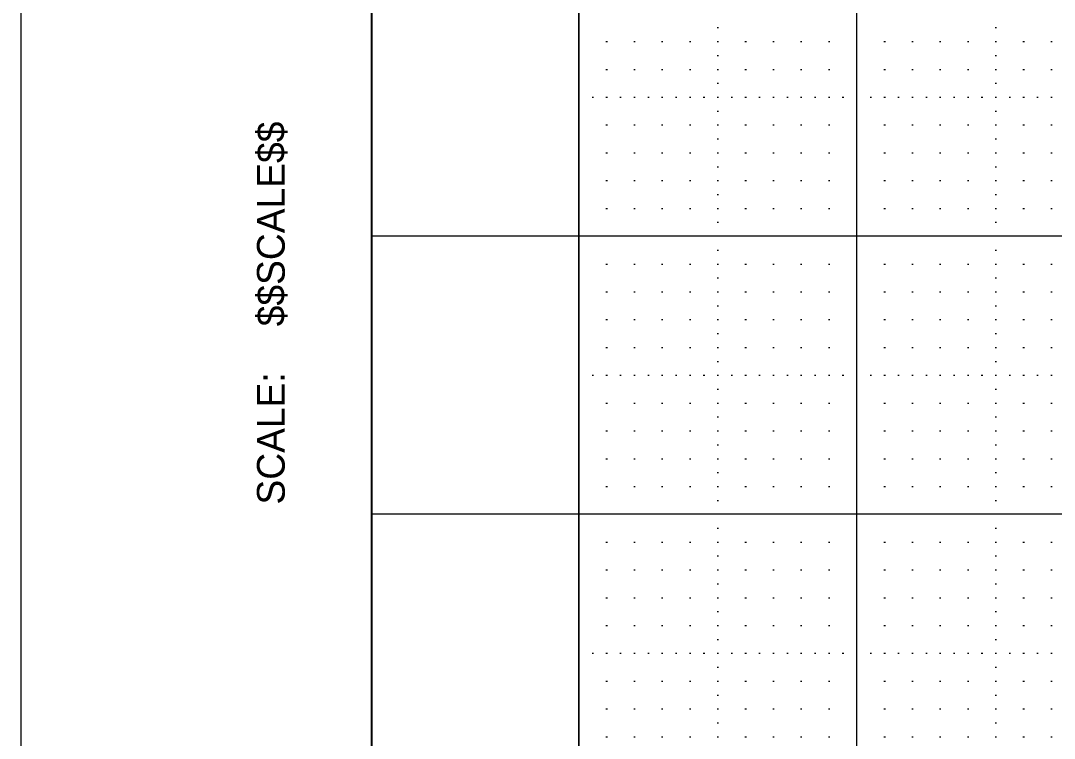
# Model space of a CAD drawing. Extents: x -1.3 to 32.1, y -0.2 to 20.7.
# Drawn here: x -1.263 to 2.455, y 2.487 to 5.068 of the extents above; entities that cross this region are included whole.
import ezdxf

# ---------------------------------------------------------------- set-up
doc = ezdxf.new("R2010")
doc.units = 0
for name, color, linetype in [('Level 1', 7, 'Continuous'), ('Level 37', 7, 'Continuous'), ('Level 4', 7, 'Continuous'), ('Level 5', 7, 'Continuous'), ('Level 62', 7, 'Continuous'), ('Level 63', 7, 'Continuous')]:
    doc.layers.add(name, color=color, linetype=linetype)

msp = doc.modelspace()

# ---------------------------------------------------------------- linework, layer by layer
at = {"layer": 'Level 1'}
msp.add_line((-0.001, -0.001), (-0.001, 20.545), dxfattribs=at)
at = {"layer": 'Level 37'}
msp.add_line((0.746, 0.6725), (0.746, 10.2935), dxfattribs=at)
at = {"layer": 'Level 4'}
for p, q in [((0.745, 0.672), (0.745, 10.293)), ((1.745, 0.672), (1.745, 10.293)), ((31.617, 4.293), (-0.001, 4.293)), ((31.617, 3.293), (-0.001, 3.293))]:
    msp.add_line(p, q, dxfattribs=at)
at = {"layer": 'Level 5'}
for p, q in [((1.2425, 5.043), (1.2475, 5.043)), ((2.2425, 5.043), (2.2475, 5.043)), ((0.8425, 4.993), (0.8475, 4.993)), ((0.9425, 4.993), (0.9475, 4.993)), ((1.0425, 4.993), (1.0475, 4.993)), ((1.1425, 4.993), (1.1475, 4.993)), ((1.2425, 4.993), (1.2475, 4.993)), ((1.3425, 4.993), (1.3475, 4.993)), ((1.4425, 4.993), (1.4475, 4.993)), ((1.5425, 4.993), (1.5475, 4.993)), ((1.6425, 4.993), (1.6475, 4.993)), ((1.8425, 4.993), (1.8475, 4.993)), ((1.9425, 4.993), (1.9475, 4.993)), ((2.0425, 4.993), (2.0475, 4.993)), ((2.1425, 4.993), (2.1475, 4.993)), ((2.2425, 4.993), (2.2475, 4.993)), ((2.3425, 4.993), (2.3475, 4.993)), ((2.4425, 4.993), (2.4475, 4.993)), ((1.2425, 4.943), (1.2475, 4.943)), ((2.2425, 4.943), (2.2475, 4.943)), ((0.8425, 4.893), (0.8475, 4.893)), ((0.9425, 4.893), (0.9475, 4.893)), ((1.0425, 4.893), (1.0475, 4.893)), ((1.1425, 4.893), (1.1475, 4.893)), ((1.2425, 4.893), (1.2475, 4.893)), ((1.3425, 4.893), (1.3475, 4.893)), ((1.4425, 4.893), (1.4475, 4.893)), ((1.5425, 4.893), (1.5475, 4.893)), ((1.6425, 4.893), (1.6475, 4.893)), ((1.8425, 4.893), (1.8475, 4.893)), ((1.9425, 4.893), (1.9475, 4.893)), ((2.0425, 4.893), (2.0475, 4.893)), ((2.1425, 4.893), (2.1475, 4.893)), ((2.2425, 4.893), (2.2475, 4.893)), ((2.3425, 4.893), (2.3475, 4.893)), ((2.4425, 4.893), (2.4475, 4.893)), ((1.2425, 4.843), (1.2475, 4.843)), ((2.2425, 4.843), (2.2475, 4.843)), ((0.7925, 4.793), (0.7975, 4.793)), ((0.8425, 4.793), (0.8475, 4.793)), ((0.8925, 4.793), (0.8975, 4.793)), ((0.9425, 4.793), (0.9475, 4.793)), ((0.9925, 4.793), (0.9975, 4.793)), ((1.0425, 4.793), (1.0475, 4.793)), ((1.0925, 4.793), (1.0975, 4.793)), ((1.1425, 4.793), (1.1475, 4.793)), ((1.1925, 4.793), (1.1975, 4.793)), ((1.2425, 4.793), (1.2475, 4.793)), ((1.2925, 4.793), (1.2975, 4.793)), ((1.3425, 4.793), (1.3475, 4.793)), ((1.3925, 4.793), (1.3975, 4.793)), ((1.4425, 4.793), (1.4475, 4.793)), ((1.4925, 4.793), (1.4975, 4.793)), ((1.5425, 4.793), (1.5475, 4.793)), ((1.5925, 4.793), (1.5975, 4.793)), ((1.6425, 4.793), (1.6475, 4.793)), ((1.6925, 4.793), (1.6975, 4.793)), ((1.7925, 4.793), (1.7975, 4.793)), ((1.8425, 4.793), (1.8475, 4.793)), ((1.8925, 4.793), (1.8975, 4.793)), ((1.9425, 4.793), (1.9475, 4.793)), ((1.9925, 4.793), (1.9975, 4.793)), ((2.0425, 4.793), (2.0475, 4.793)), ((2.0925, 4.793), (2.0975, 4.793)), ((2.1425, 4.793), (2.1475, 4.793)), ((2.1925, 4.793), (2.1975, 4.793)), ((2.2425, 4.793), (2.2475, 4.793)), ((2.2925, 4.793), (2.2975, 4.793)), ((2.3425, 4.793), (2.3475, 4.793)), ((2.3925, 4.793), (2.3975, 4.793)), ((2.4425, 4.793), (2.4475, 4.793)), ((1.2425, 4.743), (1.2475, 4.743)), ((2.2425, 4.743), (2.2475, 4.743)), ((0.8425, 4.693), (0.8475, 4.693)), ((0.9425, 4.693), (0.9475, 4.693)), ((1.0425, 4.693), (1.0475, 4.693)), ((1.1425, 4.693), (1.1475, 4.693)), ((1.2425, 4.693), (1.2475, 4.693)), ((1.3425, 4.693), (1.3475, 4.693)), ((1.4425, 4.693), (1.4475, 4.693)), ((1.5425, 4.693), (1.5475, 4.693)), ((1.6425, 4.693), (1.6475, 4.693)), ((1.8425, 4.693), (1.8475, 4.693)), ((1.9425, 4.693), (1.9475, 4.693)), ((2.0425, 4.693), (2.0475, 4.693)), ((2.1425, 4.693), (2.1475, 4.693)), ((2.2425, 4.693), (2.2475, 4.693)), ((2.3425, 4.693), (2.3475, 4.693)), ((2.4425, 4.693), (2.4475, 4.693)), ((1.2425, 4.643), (1.2475, 4.643)), ((2.2425, 4.643), (2.2475, 4.643)), ((0.8425, 4.593), (0.8475, 4.593)), ((0.9425, 4.593), (0.9475, 4.593)), ((1.0425, 4.593), (1.0475, 4.593)), ((1.1425, 4.593), (1.1475, 4.593)), ((1.2425, 4.593), (1.2475, 4.593)), ((1.3425, 4.593), (1.3475, 4.593)), ((1.4425, 4.593), (1.4475, 4.593)), ((1.5425, 4.593), (1.5475, 4.593)), ((1.6425, 4.593), (1.6475, 4.593)), ((1.8425, 4.593), (1.8475, 4.593)), ((1.9425, 4.593), (1.9475, 4.593)), ((2.0425, 4.593), (2.0475, 4.593)), ((2.1425, 4.593), (2.1475, 4.593)), ((2.2425, 4.593), (2.2475, 4.593)), ((2.3425, 4.593), (2.3475, 4.593)), ((2.4425, 4.593), (2.4475, 4.593)), ((1.2425, 4.543), (1.2475, 4.543)), ((2.2425, 4.543), (2.2475, 4.543)), ((0.8425, 4.493), (0.8475, 4.493)), ((0.9425, 4.493), (0.9475, 4.493)), ((1.0425, 4.493), (1.0475, 4.493)), ((1.1425, 4.493), (1.1475, 4.493)), ((1.2425, 4.493), (1.2475, 4.493)), ((1.3425, 4.493), (1.3475, 4.493)), ((1.4425, 4.493), (1.4475, 4.493)), ((1.5425, 4.493), (1.5475, 4.493)), ((1.6425, 4.493), (1.6475, 4.493)), ((1.8425, 4.493), (1.8475, 4.493)), ((1.9425, 4.493), (1.9475, 4.493)), ((2.0425, 4.493), (2.0475, 4.493)), ((2.1425, 4.493), (2.1475, 4.493)), ((2.2425, 4.493), (2.2475, 4.493)), ((2.3425, 4.493), (2.3475, 4.493)), ((2.4425, 4.493), (2.4475, 4.493)), ((1.2425, 4.443), (1.2475, 4.443)), ((2.2425, 4.443), (2.2475, 4.443)), ((0.8425, 4.393), (0.8475, 4.393)), ((0.9425, 4.393), (0.9475, 4.393)), ((1.0425, 4.393), (1.0475, 4.393)), ((1.1425, 4.393), (1.1475, 4.393)), ((1.2425, 4.393), (1.2475, 4.393)), ((1.3425, 4.393), (1.3475, 4.393)), ((1.4425, 4.393), (1.4475, 4.393)), ((1.5425, 4.393), (1.5475, 4.393)), ((1.6425, 4.393), (1.6475, 4.393)), ((1.8425, 4.393), (1.8475, 4.393)), ((1.9425, 4.393), (1.9475, 4.393)), ((2.0425, 4.393), (2.0475, 4.393)), ((2.1425, 4.393), (2.1475, 4.393)), ((2.2425, 4.393), (2.2475, 4.393)), ((2.3425, 4.393), (2.3475, 4.393)), ((2.4425, 4.393), (2.4475, 4.393)), ((1.2425, 4.343), (1.2475, 4.343)), ((2.2425, 4.343), (2.2475, 4.343)), ((1.2425, 4.243), (1.2475, 4.243)), ((2.2425, 4.243), (2.2475, 4.243)), ((0.8425, 4.193), (0.8475, 4.193)), ((0.9425, 4.193), (0.9475, 4.193)), ((1.0425, 4.193), (1.0475, 4.193)), ((1.1425, 4.193), (1.1475, 4.193)), ((1.2425, 4.193), (1.2475, 4.193)), ((1.3425, 4.193), (1.3475, 4.193)), ((1.4425, 4.193), (1.4475, 4.193)), ((1.5425, 4.193), (1.5475, 4.193)), ((1.6425, 4.193), (1.6475, 4.193)), ((1.8425, 4.193), (1.8475, 4.193)), ((1.9425, 4.193), (1.9475, 4.193)), ((2.0425, 4.193), (2.0475, 4.193)), ((2.1425, 4.193), (2.1475, 4.193)), ((2.2425, 4.193), (2.2475, 4.193)), ((2.3425, 4.193), (2.3475, 4.193)), ((2.4425, 4.193), (2.4475, 4.193)), ((1.2425, 4.143), (1.2475, 4.143)), ((2.2425, 4.143), (2.2475, 4.143)), ((0.8425, 4.093), (0.8475, 4.093)), ((0.9425, 4.093), (0.9475, 4.093)), ((1.0425, 4.093), (1.0475, 4.093)), ((1.1425, 4.093), (1.1475, 4.093)), ((1.2425, 4.093), (1.2475, 4.093)), ((1.3425, 4.093), (1.3475, 4.093)), ((1.4425, 4.093), (1.4475, 4.093)), ((1.5425, 4.093), (1.5475, 4.093)), ((1.6425, 4.093), (1.6475, 4.093)), ((1.8425, 4.093), (1.8475, 4.093)), ((1.9425, 4.093), (1.9475, 4.093)), ((2.0425, 4.093), (2.0475, 4.093)), ((2.1425, 4.093), (2.1475, 4.093)), ((2.2425, 4.093), (2.2475, 4.093)), ((2.3425, 4.093), (2.3475, 4.093)), ((2.4425, 4.093), (2.4475, 4.093)), ((1.2425, 4.043), (1.2475, 4.043)), ((2.2425, 4.043), (2.2475, 4.043)), ((0.8425, 3.993), (0.8475, 3.993)), ((0.9425, 3.993), (0.9475, 3.993)), ((1.0425, 3.993), (1.0475, 3.993)), ((1.1425, 3.993), (1.1475, 3.993)), ((1.2425, 3.993), (1.2475, 3.993)), ((1.3425, 3.993), (1.3475, 3.993)), ((1.4425, 3.993), (1.4475, 3.993)), ((1.5425, 3.993), (1.5475, 3.993)), ((1.6425, 3.993), (1.6475, 3.993)), ((1.8425, 3.993), (1.8475, 3.993)), ((1.9425, 3.993), (1.9475, 3.993)), ((2.0425, 3.993), (2.0475, 3.993)), ((2.1425, 3.993), (2.1475, 3.993)), ((2.2425, 3.993), (2.2475, 3.993)), ((2.3425, 3.993), (2.3475, 3.993)), ((2.4425, 3.993), (2.4475, 3.993)), ((1.2425, 3.943), (1.2475, 3.943)), ((2.2425, 3.943), (2.2475, 3.943)), ((0.8425, 3.893), (0.8475, 3.893)), ((0.9425, 3.893), (0.9475, 3.893)), ((1.0425, 3.893), (1.0475, 3.893)), ((1.1425, 3.893), (1.1475, 3.893)), ((1.2425, 3.893), (1.2475, 3.893)), ((1.3425, 3.893), (1.3475, 3.893)), ((1.4425, 3.893), (1.4475, 3.893)), ((1.5425, 3.893), (1.5475, 3.893)), ((1.6425, 3.893), (1.6475, 3.893)), ((1.8425, 3.893), (1.8475, 3.893)), ((1.9425, 3.893), (1.9475, 3.893)), ((2.0425, 3.893), (2.0475, 3.893)), ((2.1425, 3.893), (2.1475, 3.893)), ((2.2425, 3.893), (2.2475, 3.893)), ((2.3425, 3.893), (2.3475, 3.893)), ((2.4425, 3.893), (2.4475, 3.893)), ((1.2425, 3.843), (1.2475, 3.843)), ((2.2425, 3.843), (2.2475, 3.843)), ((0.7925, 3.793), (0.7975, 3.793)), ((0.8425, 3.793), (0.8475, 3.793)), ((0.8925, 3.793), (0.8975, 3.793)), ((0.9425, 3.793), (0.9475, 3.793)), ((0.9925, 3.793), (0.9975, 3.793)), ((1.0425, 3.793), (1.0475, 3.793)), ((1.0925, 3.793), (1.0975, 3.793)), ((1.1425, 3.793), (1.1475, 3.793)), ((1.1925, 3.793), (1.1975, 3.793)), ((1.2425, 3.793), (1.2475, 3.793)), ((1.2925, 3.793), (1.2975, 3.793)), ((1.3425, 3.793), (1.3475, 3.793)), ((1.3925, 3.793), (1.3975, 3.793)), ((1.4425, 3.793), (1.4475, 3.793)), ((1.4925, 3.793), (1.4975, 3.793)), ((1.5425, 3.793), (1.5475, 3.793)), ((1.5925, 3.793), (1.5975, 3.793)), ((1.6425, 3.793), (1.6475, 3.793)), ((1.6925, 3.793), (1.6975, 3.793)), ((1.7925, 3.793), (1.7975, 3.793)), ((1.8425, 3.793), (1.8475, 3.793)), ((1.8925, 3.793), (1.8975, 3.793)), ((1.9425, 3.793), (1.9475, 3.793)), ((1.9925, 3.793), (1.9975, 3.793)), ((2.0425, 3.793), (2.0475, 3.793)), ((2.0925, 3.793), (2.0975, 3.793)), ((2.1425, 3.793), (2.1475, 3.793)), ((2.1925, 3.793), (2.1975, 3.793)), ((2.2425, 3.793), (2.2475, 3.793)), ((2.2925, 3.793), (2.2975, 3.793)), ((2.3425, 3.793), (2.3475, 3.793)), ((2.3925, 3.793), (2.3975, 3.793)), ((2.4425, 3.793), (2.4475, 3.793)), ((1.2425, 3.743), (1.2475, 3.743)), ((2.2425, 3.743), (2.2475, 3.743)), ((0.8425, 3.693), (0.8475, 3.693)), ((0.9425, 3.693), (0.9475, 3.693)), ((1.0425, 3.693), (1.0475, 3.693)), ((1.1425, 3.693), (1.1475, 3.693)), ((1.2425, 3.693), (1.2475, 3.693)), ((1.3425, 3.693), (1.3475, 3.693)), ((1.4425, 3.693), (1.4475, 3.693)), ((1.5425, 3.693), (1.5475, 3.693)), ((1.6425, 3.693), (1.6475, 3.693)), ((1.8425, 3.693), (1.8475, 3.693)), ((1.9425, 3.693), (1.9475, 3.693)), ((2.0425, 3.693), (2.0475, 3.693)), ((2.1425, 3.693), (2.1475, 3.693)), ((2.2425, 3.693), (2.2475, 3.693)), ((2.3425, 3.693), (2.3475, 3.693)), ((2.4425, 3.693), (2.4475, 3.693)), ((1.2425, 3.643), (1.2475, 3.643)), ((2.2425, 3.643), (2.2475, 3.643)), ((0.8425, 3.593), (0.8475, 3.593)), ((0.9425, 3.593), (0.9475, 3.593)), ((1.0425, 3.593), (1.0475, 3.593)), ((1.1425, 3.593), (1.1475, 3.593)), ((1.2425, 3.593), (1.2475, 3.593)), ((1.3425, 3.593), (1.3475, 3.593)), ((1.4425, 3.593), (1.4475, 3.593)), ((1.5425, 3.593), (1.5475, 3.593)), ((1.6425, 3.593), (1.6475, 3.593)), ((1.8425, 3.593), (1.8475, 3.593)), ((1.9425, 3.593), (1.9475, 3.593)), ((2.0425, 3.593), (2.0475, 3.593)), ((2.1425, 3.593), (2.1475, 3.593)), ((2.2425, 3.593), (2.2475, 3.593)), ((2.3425, 3.593), (2.3475, 3.593)), ((2.4425, 3.593), (2.4475, 3.593)), ((1.2425, 3.543), (1.2475, 3.543)), ((2.2425, 3.543), (2.2475, 3.543)), ((0.8425, 3.493), (0.8475, 3.493)), ((0.9425, 3.493), (0.9475, 3.493)), ((1.0425, 3.493), (1.0475, 3.493)), ((1.1425, 3.493), (1.1475, 3.493)), ((1.2425, 3.493), (1.2475, 3.493)), ((1.3425, 3.493), (1.3475, 3.493)), ((1.4425, 3.493), (1.4475, 3.493)), ((1.5425, 3.493), (1.5475, 3.493)), ((1.6425, 3.493), (1.6475, 3.493)), ((1.8425, 3.493), (1.8475, 3.493)), ((1.9425, 3.493), (1.9475, 3.493)), ((2.0425, 3.493), (2.0475, 3.493)), ((2.1425, 3.493), (2.1475, 3.493)), ((2.2425, 3.493), (2.2475, 3.493)), ((2.3425, 3.493), (2.3475, 3.493)), ((2.4425, 3.493), (2.4475, 3.493)), ((1.2425, 3.443), (1.2475, 3.443)), ((2.2425, 3.443), (2.2475, 3.443)), ((0.8425, 3.393), (0.8475, 3.393)), ((0.9425, 3.393), (0.9475, 3.393)), ((1.0425, 3.393), (1.0475, 3.393)), ((1.1425, 3.393), (1.1475, 3.393)), ((1.2425, 3.393), (1.2475, 3.393)), ((1.3425, 3.393), (1.3475, 3.393)), ((1.4425, 3.393), (1.4475, 3.393)), ((1.5425, 3.393), (1.5475, 3.393)), ((1.6425, 3.393), (1.6475, 3.393)), ((1.8425, 3.393), (1.8475, 3.393)), ((1.9425, 3.393), (1.9475, 3.393)), ((2.0425, 3.393), (2.0475, 3.393)), ((2.1425, 3.393), (2.1475, 3.393)), ((2.2425, 3.393), (2.2475, 3.393)), ((2.3425, 3.393), (2.3475, 3.393)), ((2.4425, 3.393), (2.4475, 3.393)), ((1.2425, 3.343), (1.2475, 3.343)), ((2.2425, 3.343), (2.2475, 3.343)), ((1.2425, 3.243), (1.2475, 3.243)), ((2.2425, 3.243), (2.2475, 3.243)), ((0.8425, 3.193), (0.8475, 3.193)), ((0.9425, 3.193), (0.9475, 3.193)), ((1.0425, 3.193), (1.0475, 3.193)), ((1.1425, 3.193), (1.1475, 3.193)), ((1.2425, 3.193), (1.2475, 3.193)), ((1.3425, 3.193), (1.3475, 3.193)), ((1.4425, 3.193), (1.4475, 3.193)), ((1.5425, 3.193), (1.5475, 3.193)), ((1.6425, 3.193), (1.6475, 3.193)), ((1.8425, 3.193), (1.8475, 3.193)), ((1.9425, 3.193), (1.9475, 3.193)), ((2.0425, 3.193), (2.0475, 3.193)), ((2.1425, 3.193), (2.1475, 3.193)), ((2.2425, 3.193), (2.2475, 3.193)), ((2.3425, 3.193), (2.3475, 3.193)), ((2.4425, 3.193), (2.4475, 3.193)), ((1.2425, 3.143), (1.2475, 3.143)), ((2.2425, 3.143), (2.2475, 3.143)), ((0.8425, 3.093), (0.8475, 3.093)), ((0.9425, 3.093), (0.9475, 3.093)), ((1.0425, 3.093), (1.0475, 3.093)), ((1.1425, 3.093), (1.1475, 3.093)), ((1.2425, 3.093), (1.2475, 3.093)), ((1.3425, 3.093), (1.3475, 3.093)), ((1.4425, 3.093), (1.4475, 3.093)), ((1.5425, 3.093), (1.5475, 3.093)), ((1.6425, 3.093), (1.6475, 3.093)), ((1.8425, 3.093), (1.8475, 3.093)), ((1.9425, 3.093), (1.9475, 3.093)), ((2.0425, 3.093), (2.0475, 3.093)), ((2.1425, 3.093), (2.1475, 3.093)), ((2.2425, 3.093), (2.2475, 3.093)), ((2.3425, 3.093), (2.3475, 3.093)), ((2.4425, 3.093), (2.4475, 3.093)), ((1.2425, 3.043), (1.2475, 3.043)), ((2.2425, 3.043), (2.2475, 3.043)), ((0.8425, 2.993), (0.8475, 2.993)), ((0.9425, 2.993), (0.9475, 2.993)), ((1.0425, 2.993), (1.0475, 2.993)), ((1.1425, 2.993), (1.1475, 2.993)), ((1.2425, 2.993), (1.2475, 2.993)), ((1.3425, 2.993), (1.3475, 2.993)), ((1.4425, 2.993), (1.4475, 2.993)), ((1.5425, 2.993), (1.5475, 2.993)), ((1.6425, 2.993), (1.6475, 2.993)), ((1.8425, 2.993), (1.8475, 2.993)), ((1.9425, 2.993), (1.9475, 2.993)), ((2.0425, 2.993), (2.0475, 2.993)), ((2.1425, 2.993), (2.1475, 2.993)), ((2.2425, 2.993), (2.2475, 2.993)), ((2.3425, 2.993), (2.3475, 2.993)), ((2.4425, 2.993), (2.4475, 2.993)), ((1.2425, 2.943), (1.2475, 2.943)), ((2.2425, 2.943), (2.2475, 2.943)), ((0.8425, 2.893), (0.8475, 2.893)), ((0.9425, 2.893), (0.9475, 2.893)), ((1.0425, 2.893), (1.0475, 2.893)), ((1.1425, 2.893), (1.1475, 2.893)), ((1.2425, 2.893), (1.2475, 2.893)), ((1.3425, 2.893), (1.3475, 2.893)), ((1.4425, 2.893), (1.4475, 2.893)), ((1.5425, 2.893), (1.5475, 2.893)), ((1.6425, 2.893), (1.6475, 2.893)), ((1.8425, 2.893), (1.8475, 2.893)), ((1.9425, 2.893), (1.9475, 2.893)), ((2.0425, 2.893), (2.0475, 2.893)), ((2.1425, 2.893), (2.1475, 2.893)), ((2.2425, 2.893), (2.2475, 2.893)), ((2.3425, 2.893), (2.3475, 2.893)), ((2.4425, 2.893), (2.4475, 2.893)), ((1.2425, 2.843), (1.2475, 2.843)), ((2.2425, 2.843), (2.2475, 2.843)), ((0.7925, 2.793), (0.7975, 2.793)), ((0.8425, 2.793), (0.8475, 2.793)), ((0.8925, 2.793), (0.8975, 2.793)), ((0.9425, 2.793), (0.9475, 2.793)), ((0.9925, 2.793), (0.9975, 2.793)), ((1.0425, 2.793), (1.0475, 2.793)), ((1.0925, 2.793), (1.0975, 2.793)), ((1.1425, 2.793), (1.1475, 2.793)), ((1.1925, 2.793), (1.1975, 2.793)), ((1.2425, 2.793), (1.2475, 2.793)), ((1.2925, 2.793), (1.2975, 2.793)), ((1.3425, 2.793), (1.3475, 2.793)), ((1.3925, 2.793), (1.3975, 2.793)), ((1.4425, 2.793), (1.4475, 2.793)), ((1.4925, 2.793), (1.4975, 2.793)), ((1.5425, 2.793), (1.5475, 2.793)), ((1.5925, 2.793), (1.5975, 2.793)), ((1.6425, 2.793), (1.6475, 2.793)), ((1.6925, 2.793), (1.6975, 2.793)), ((1.7925, 2.793), (1.7975, 2.793)), ((1.8425, 2.793), (1.8475, 2.793)), ((1.8925, 2.793), (1.8975, 2.793)), ((1.9425, 2.793), (1.9475, 2.793)), ((1.9925, 2.793), (1.9975, 2.793)), ((2.0425, 2.793), (2.0475, 2.793)), ((2.0925, 2.793), (2.0975, 2.793)), ((2.1425, 2.793), (2.1475, 2.793)), ((2.1925, 2.793), (2.1975, 2.793)), ((2.2425, 2.793), (2.2475, 2.793)), ((2.2925, 2.793), (2.2975, 2.793)), ((2.3425, 2.793), (2.3475, 2.793)), ((2.3925, 2.793), (2.3975, 2.793)), ((2.4425, 2.793), (2.4475, 2.793)), ((1.2425, 2.743), (1.2475, 2.743)), ((2.2425, 2.743), (2.2475, 2.743)), ((0.8425, 2.693), (0.8475, 2.693)), ((0.9425, 2.693), (0.9475, 2.693)), ((1.0425, 2.693), (1.0475, 2.693)), ((1.1425, 2.693), (1.1475, 2.693)), ((1.2425, 2.693), (1.2475, 2.693)), ((1.3425, 2.693), (1.3475, 2.693)), ((1.4425, 2.693), (1.4475, 2.693)), ((1.5425, 2.693), (1.5475, 2.693)), ((1.6425, 2.693), (1.6475, 2.693)), ((1.8425, 2.693), (1.8475, 2.693)), ((1.9425, 2.693), (1.9475, 2.693)), ((2.0425, 2.693), (2.0475, 2.693)), ((2.1425, 2.693), (2.1475, 2.693)), ((2.2425, 2.693), (2.2475, 2.693)), ((2.3425, 2.693), (2.3475, 2.693)), ((2.4425, 2.693), (2.4475, 2.693)), ((1.2425, 2.643), (1.2475, 2.643)), ((2.2425, 2.643), (2.2475, 2.643)), ((0.8425, 2.593), (0.8475, 2.593)), ((0.9425, 2.593), (0.9475, 2.593)), ((1.0425, 2.593), (1.0475, 2.593)), ((1.1425, 2.593), (1.1475, 2.593)), ((1.2425, 2.593), (1.2475, 2.593)), ((1.3425, 2.593), (1.3475, 2.593)), ((1.4425, 2.593), (1.4475, 2.593)), ((1.5425, 2.593), (1.5475, 2.593)), ((1.6425, 2.593), (1.6475, 2.593)), ((1.8425, 2.593), (1.8475, 2.593)), ((1.9425, 2.593), (1.9475, 2.593)), ((2.0425, 2.593), (2.0475, 2.593)), ((2.1425, 2.593), (2.1475, 2.593)), ((2.2425, 2.593), (2.2475, 2.593)), ((2.3425, 2.593), (2.3475, 2.593)), ((2.4425, 2.593), (2.4475, 2.593)), ((1.2425, 2.543), (1.2475, 2.543)), ((2.2425, 2.543), (2.2475, 2.543)), ((0.8425, 2.493), (0.8475, 2.493)), ((0.9425, 2.493), (0.9475, 2.493)), ((1.0425, 2.493), (1.0475, 2.493)), ((1.1425, 2.493), (1.1475, 2.493)), ((1.2425, 2.493), (1.2475, 2.493)), ((1.3425, 2.493), (1.3475, 2.493)), ((1.4425, 2.493), (1.4475, 2.493)), ((1.5425, 2.493), (1.5475, 2.493)), ((1.6425, 2.493), (1.6475, 2.493)), ((1.8425, 2.493), (1.8475, 2.493)), ((1.9425, 2.493), (1.9475, 2.493)), ((2.0425, 2.493), (2.0475, 2.493)), ((2.1425, 2.493), (2.1475, 2.493)), ((2.2425, 2.493), (2.2475, 2.493)), ((2.3425, 2.493), (2.3475, 2.493)), ((2.4425, 2.493), (2.4475, 2.493))]:
    msp.add_line(p, q, dxfattribs=at)
at = {"layer": 'Level 62'}
msp.add_line((0, 10.294), (0, 0.6734), dxfattribs=at)
at = {"layer": 'Level 63'}
msp.add_lwpolyline([(-1.263, -0.2005), (32.067, -0.2005), (32.067, 20.7465), (-1.263, 20.7465)], close=True, dxfattribs=at)

# ---------------------------------------------------------------- texts
at = {"layer": 'Level 1'}
for s, p in [('$$SCALE$$', (-0.313, 3.969)), ('SCALE:', (-0.313, 3.328))]:
    msp.add_text(s, height=0.1, rotation=90, dxfattribs=at).set_placement(p)

doc.saveas('drawing.dxf')
